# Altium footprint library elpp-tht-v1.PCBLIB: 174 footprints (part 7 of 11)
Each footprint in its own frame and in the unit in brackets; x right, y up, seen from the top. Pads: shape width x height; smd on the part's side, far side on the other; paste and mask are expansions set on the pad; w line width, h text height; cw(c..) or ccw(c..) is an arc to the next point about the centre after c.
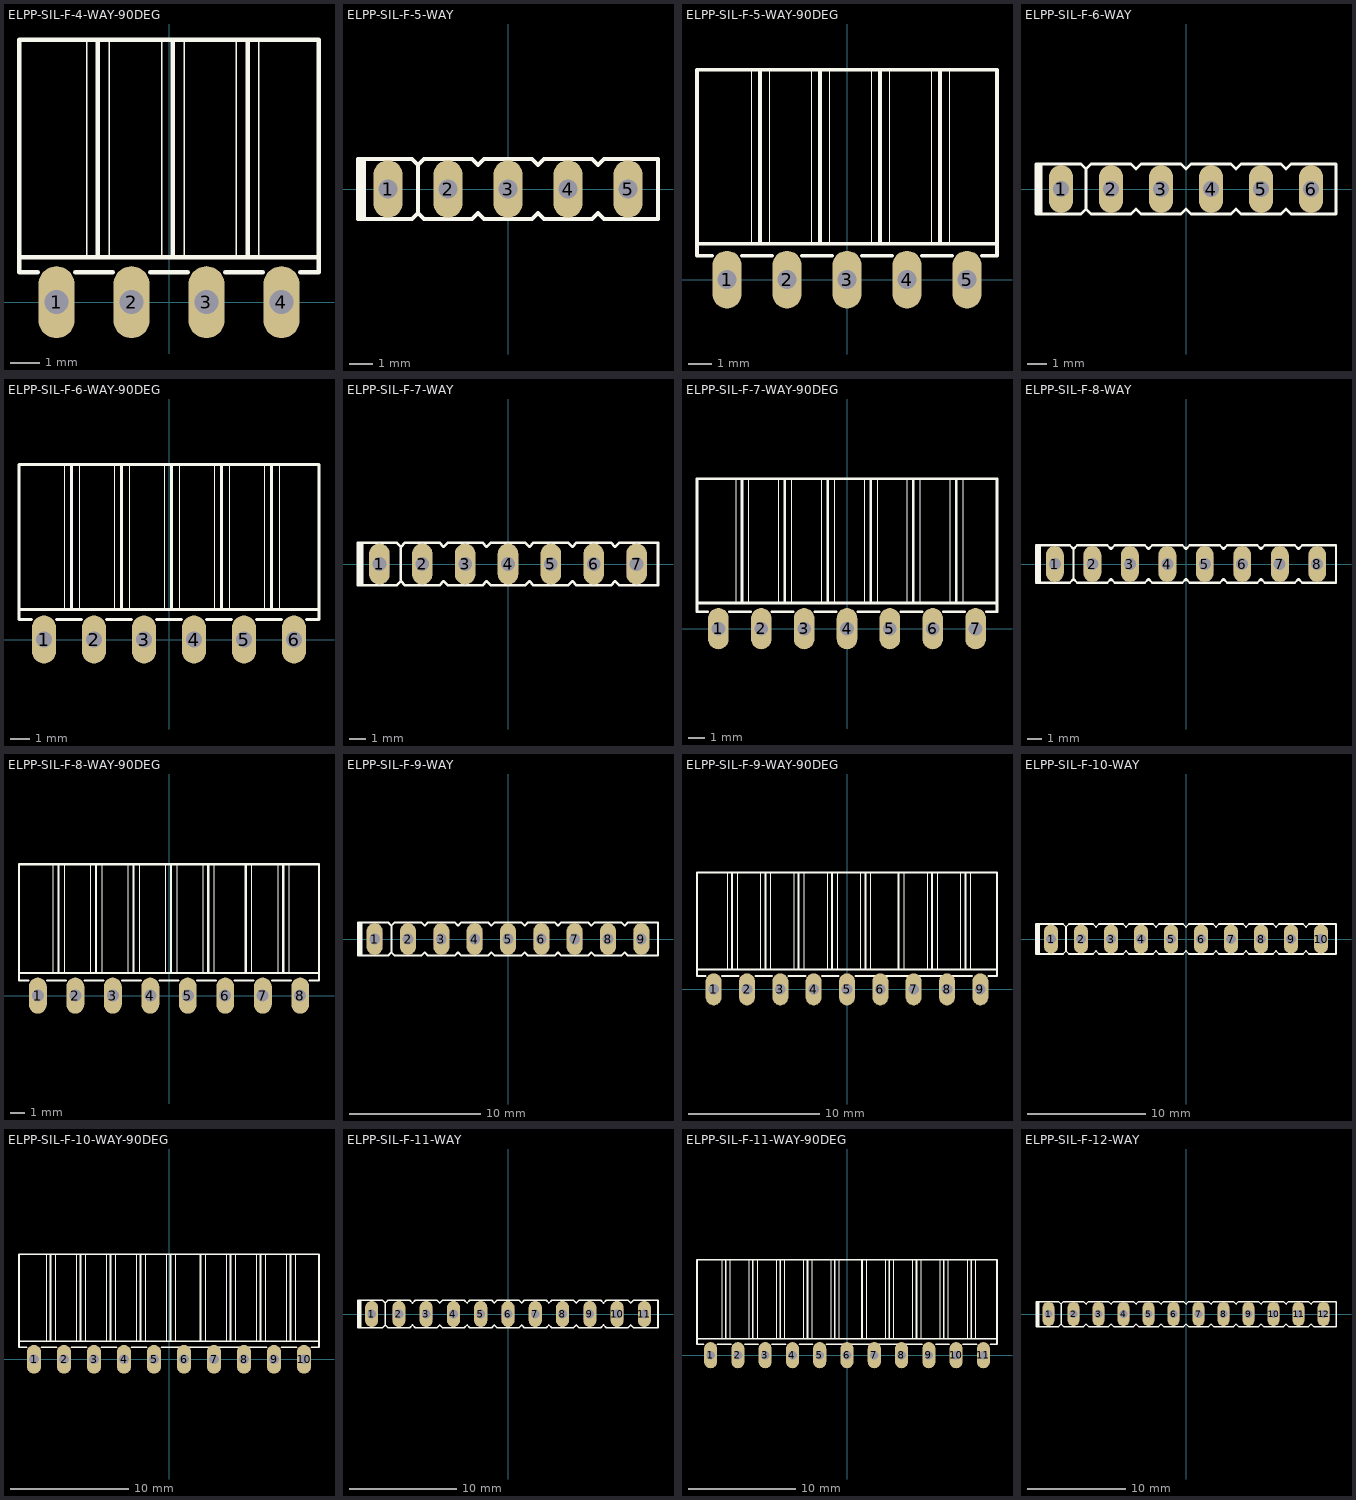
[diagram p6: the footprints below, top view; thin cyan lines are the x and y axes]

## ELPP-SIL-F-4-WAY-90DEG [mil]
pads (4):
  oval 48x96 hole 32: 1(-150,0) 2(-50,0) 3(50,0) 4(150,0)
Top Overlay:
  lines w2: -110,60 -110,350 ; -80,60 -80,350 ; -10,60 -10,350 ; 20,60 20,350 ; 90,60 90,350 ; 120,60 120,350
  lines w6: -175,40 -200,40 -200,60 ; -125,40 -75,40 ; -25,40 25,40 ; 75,40 125,40 ; 175,40 200,40 200,60 ; -200,60 -200,350 -110,350 -95,350 ; -200,60 -110,60 -95,60 ; -95,60 -80,60 -10,60 5,60 ; -95,60 -95,350 ; -95,350 -80,350 -10,350 5,350 ; 5,60 20,60 90,60 105,60 ; 5,60 5,350 ; 5,350 20,350 90,350 105,350 ; 105,60 120,60 200,60 ; 105,60 105,350 ; 105,350 120,350 200,350 200,60
Mechanical 2:
  text ">NAME" at -220,40 h42.5
Mechanical 4:
  text ">VALUE" at -150,-110 h42.5
Mechanical 16:
  rectangle: -160,0 -140,40
  rectangle: -60,0 -40,40
  rectangle: 40,0 60,40
  rectangle: 140,0 160,40
  text "2" at -20,100 h77.5
  text "3" at 80,100 h77.5
  text "4" at 180,100 h77.5
  text "1" at -120,100 h77.5

## ELPP-SIL-F-5-WAY [mil]
pads (5):
  oval 48x96 hole 32: 1(-200,0) 2(-100,0) 3(0,0) 4(100,0) 5(200,0)
Top Overlay:
  lines w6: -245,-50 -250,-50 -250,50 -245,50 ; -245,-50 -240,-50 ; -245,-50 -245,50 ; -245,50 -240,50 ; -240,-50 -160,-50 -150,-40 ; -240,-50 -240,50 ; -240,50 -160,50 -150,40 ; -150,-40 -140,-50 -60,-50 -50,-40 -40,-50 40,-50 50,-40 60,-50 140,-50 150,-40 160,-50 250,-50 250,50 160,50 150,40 140,50 60,50 50,40 40,50 -40,50 -50,40 -60,50 -140,50 -150,40 ; -150,-40 -150,40
Mechanical 2:
  text ">NAME" at -250,65 h42.5
Mechanical 4:
  text ">VALUE" at 0,65 h42.5
Mechanical 16:
  rectangle: -205,10 -195,30
  rectangle: -205,-30 -195,-10
  rectangle: -105,10 -95,30
  rectangle: -105,-30 -95,-10
  rectangle: -5,10 5,30
  rectangle: -5,-30 5,-10
  rectangle: 95,10 105,30
  rectangle: 95,-30 105,-10
  rectangle: 195,10 205,30
  rectangle: 195,-30 205,-10
  lines w6: -220,-20 -220,20 -210,20 -210,30 -190,30 -190,20 -180,20 -180,-20 -190,-20 -190,-30 -210,-30 -210,-20 -220,-20 ; -120,-20 -120,20 -110,20 -110,30 -90,30 -90,20 -80,20 -80,-20 -90,-20 -90,-30 -110,-30 -110,-20 -120,-20 ; -20,-20 -20,20 -10,20 -10,30 10,30 10,20 20,20 20,-20 10,-20 10,-30 -10,-30 -10,-20 -20,-20 ; 80,-20 80,20 90,20 90,30 110,30 110,20 120,20 120,-20 110,-20 110,-30 90,-30 90,-20 80,-20 ; 180,-20 180,20 190,20 190,30 210,30 210,20 220,20 220,-20 210,-20 210,-30 190,-30 190,-20 180,-20

## ELPP-SIL-F-5-WAY-90DEG [mil]
pads (5):
  oval 48x96 hole 32: 1(-200,0) 2(-100,0) 3(0,0) 4(100,0) 5(200,0)
Top Overlay:
  lines w2: -160,60 -160,350 ; -130,60 -130,350 ; -60,60 -60,350 ; -30,60 -30,350 ; 40,60 40,350 ; 70,60 70,350 ; 140,60 140,350 ; 170,60 170,350
  lines w6: -225,40 -250,40 -250,60 ; -175,40 -125,40 ; -75,40 -25,40 ; 25,40 75,40 ; 125,40 175,40 ; 225,40 250,40 250,60 ; -250,60 -250,350 -160,350 -145,350 ; -250,60 -160,60 -145,60 ; -145,60 -130,60 -60,60 -45,60 ; -145,60 -145,350 ; -145,350 -130,350 -60,350 -45,350 ; -45,60 -30,60 40,60 55,60 ; -45,60 -45,350 ; -45,350 -30,350 40,350 55,350 ; 55,60 70,60 140,60 155,60 ; 55,60 55,350 ; 55,350 70,350 140,350 155,350 ; 155,60 170,60 250,60 ; 155,60 155,350 ; 155,350 170,350 250,350 250,60
Mechanical 2:
  text ">NAME" at -270,40 h42.5
Mechanical 4:
  text ">VALUE" at 310,50 h42.5
Mechanical 16:
  rectangle: -210,0 -190,40
  rectangle: -110,0 -90,40
  rectangle: -10,0 10,40
  rectangle: 90,0 110,40
  rectangle: 190,0 210,40
  text "2" at -70,100 h77.5
  text "5" at 235,100 h77.5
  text "3" at 30,100 h77.5
  text "4" at 130,100 h77.5
  text "1" at -170,100 h77.5

## ELPP-SIL-F-6-WAY [mil]
pads (6):
  oval 48x96 hole 32: 1(-250,0) 2(-150,0) 3(-50,0) 4(50,0) 5(150,0) 6(250,0)
Top Overlay:
  lines w6: -295,-50 -300,-50 -300,50 -295,50 ; -295,-50 -290,-50 ; -295,-50 -295,50 ; -295,50 -290,50 ; -290,-50 -210,-50 -200,-40 ; -290,-50 -290,50 ; -290,50 -210,50 -200,40 ; -200,-40 -190,-50 -110,-50 -100,-40 -90,-50 -10,-50 0,-40 10,-50 90,-50 100,-40 110,-50 190,-50 200,-40 210,-50 300,-50 300,50 210,50 200,40 190,50 110,50 100,40 90,50 10,50 0,40 -10,50 -90,50 -100,40 -110,50 -190,50 -200,40 ; -200,-40 -200,40
Mechanical 2:
  text ">NAME" at -300,65 h42.5
Mechanical 4:
  text ">VALUE" at 0,65 h42.5
Mechanical 16:
  rectangle: -255,10 -245,30
  rectangle: -255,-30 -245,-10
  rectangle: -155,10 -145,30
  rectangle: -155,-30 -145,-10
  rectangle: -55,10 -45,30
  rectangle: -55,-30 -45,-10
  rectangle: 45,10 55,30
  rectangle: 45,-30 55,-10
  rectangle: 145,10 155,30
  rectangle: 145,-30 155,-10
  rectangle: 245,10 255,30
  rectangle: 245,-30 255,-10
  lines w6: -270,-20 -270,20 -260,20 -260,30 -240,30 -240,20 -230,20 -230,-20 -240,-20 -240,-30 -260,-30 -260,-20 -270,-20 ; -170,-20 -170,20 -160,20 -160,30 -140,30 -140,20 -130,20 -130,-20 -140,-20 -140,-30 -160,-30 -160,-20 -170,-20 ; -70,-20 -70,20 -60,20 -60,30 -40,30 -40,20 -30,20 -30,-20 -40,-20 -40,-30 -60,-30 -60,-20 -70,-20 ; 30,-20 30,20 40,20 40,30 60,30 60,20 70,20 70,-20 60,-20 60,-30 40,-30 40,-20 30,-20 ; 130,-20 130,20 140,20 140,30 160,30 160,20 170,20 170,-20 160,-20 160,-30 140,-30 140,-20 130,-20 ; 230,-20 230,20 240,20 240,30 260,30 260,20 270,20 270,-20 260,-20 260,-30 240,-30 240,-20 230,-20

## ELPP-SIL-F-6-WAY-90DEG [mil]
pads (6):
  oval 48x96 hole 32: 1(-250,0) 2(-150,0) 3(-50,0) 4(50,0) 5(150,0) 6(250,0)
Top Overlay:
  lines w2: -210,60 -210,350 ; -180,60 -180,350 ; -110,60 -110,350 ; -80,60 -80,350 ; -10,60 -10,350 ; 20,60 20,350 ; 90,60 90,350 ; 120,60 120,350 ; 190,60 190,350 ; 220,60 220,350
  lines w6: -275,40 -300,40 -300,60 ; -225,40 -175,40 ; -125,40 -75,40 ; -25,40 25,40 ; 75,40 125,40 ; 175,40 225,40 ; 220,60 205,60 ; 220,350 205,350 ; 275,40 300,40 300,60 ; -300,60 -300,350 -210,350 -195,350 ; -300,60 -210,60 -195,60 ; -195,60 -180,60 -110,60 -95,60 ; -195,60 -195,350 ; -195,350 -180,350 -110,350 -95,350 ; -95,60 -80,60 -10,60 5,60 ; -95,60 -95,350 ; -95,350 -80,350 -10,350 5,350 ; 5,60 20,60 90,60 105,60 ; 5,60 5,350 ; 5,350 20,350 90,350 105,350 ; 105,60 120,60 ; 105,60 105,350 ; 105,350 120,350 ; 120,60 300,60 ; 120,60 190,60 205,60 ; 120,350 300,350 300,60 ; 120,350 190,350 205,350 ; 205,60 205,350
Mechanical 2:
  text ">NAME" at -320,40 h42.5
Mechanical 4:
  text ">VALUE" at 360,50 h42.5
Mechanical 16:
  rectangle: -260,0 -240,40
  rectangle: -160,0 -140,40
  rectangle: -60,0 -40,40
  rectangle: 40,0 60,40
  rectangle: 140,0 160,40
  rectangle: 240,0 260,40
  text "2" at -120,100 h77.5
  text "5" at 185,100 h77.5
  text "3" at -20,100 h77.5
  text "4" at 80,100 h77.5
  text "1" at -220,100 h77.5
  text "6" at 285,100 h77.5

## ELPP-SIL-F-7-WAY [mil]
pads (7):
  oval 48x96 hole 32: 1(-300,0) 2(-200,0) 3(-100,0) 4(0,0) 5(100,0) 6(200,0) 7(300,0)
Top Overlay:
  lines w6: -345,-50 -350,-50 -350,50 -345,50 ; -345,-50 -340,-50 ; -345,-50 -345,50 ; -345,50 -340,50 ; -340,-50 -260,-50 -250,-40 ; -340,-50 -340,50 ; -340,50 -260,50 -250,40 ; -250,-40 -240,-50 -160,-50 -150,-40 -140,-50 -60,-50 -50,-40 -40,-50 40,-50 50,-40 60,-50 140,-50 150,-40 160,-50 240,-50 250,-40 260,-50 350,-50 350,50 260,50 250,40 240,50 160,50 150,40 140,50 60,50 50,40 40,50 -40,50 -50,40 -60,50 -140,50 -150,40 -160,50 -240,50 -250,40 ; -250,-40 -250,40
Mechanical 2:
  text ">NAME" at -350,65 h42.5
Mechanical 4:
  text ">VALUE" at 50,65 h42.5
Mechanical 16:
  rectangle: -305,10 -295,30
  rectangle: -305,-30 -295,-10
  rectangle: -205,10 -195,30
  rectangle: -205,-30 -195,-10
  rectangle: -105,10 -95,30
  rectangle: -105,-30 -95,-10
  rectangle: -5,10 5,30
  rectangle: -5,-30 5,-10
  rectangle: 95,10 105,30
  rectangle: 95,-30 105,-10
  rectangle: 195,10 205,30
  rectangle: 195,-30 205,-10
  rectangle: 295,10 305,30
  rectangle: 295,-30 305,-10
  lines w6: -320,-20 -320,20 -310,20 -310,30 -290,30 -290,20 -280,20 -280,-20 -290,-20 -290,-30 -310,-30 -310,-20 -320,-20 ; -220,-20 -220,20 -210,20 -210,30 -190,30 -190,20 -180,20 -180,-20 -190,-20 -190,-30 -210,-30 -210,-20 -220,-20 ; -120,-20 -120,20 -110,20 -110,30 -90,30 -90,20 -80,20 -80,-20 -90,-20 -90,-30 -110,-30 -110,-20 -120,-20 ; -20,-20 -20,20 -10,20 -10,30 10,30 10,20 20,20 20,-20 10,-20 10,-30 -10,-30 -10,-20 -20,-20 ; 80,-20 80,20 90,20 90,30 110,30 110,20 120,20 120,-20 110,-20 110,-30 90,-30 90,-20 80,-20 ; 180,-20 180,20 190,20 190,30 210,30 210,20 220,20 220,-20 210,-20 210,-30 190,-30 190,-20 180,-20 ; 280,-20 280,20 290,20 290,30 310,30 310,20 320,20 320,-20 310,-20 310,-30 290,-30 290,-20 280,-20

## ELPP-SIL-F-7-WAY-90DEG [mil]
pads (7):
  oval 48x96 hole 32: 1(-300,0) 2(-200,0) 3(-100,0) 4(0,0) 5(100,0) 6(200,0) 7(300,0)
Top Overlay:
  lines w2: -260,60 -260,350 ; -230,60 -230,350 ; -160,60 -160,350 ; -130,60 -130,350 ; -60,60 -60,350 ; -30,60 -30,350 ; 40,60 40,350 ; 70,60 70,350 ; 140,60 140,350 ; 170,60 170,350 ; 240,60 240,350 ; 270,60 270,350
  lines w6: -325,40 -350,40 -350,60 ; -275,40 -225,40 ; -175,40 -125,40 ; -75,40 -25,40 ; 25,40 75,40 ; 125,40 175,40 ; 170,60 155,60 ; 170,350 155,350 ; 225,40 275,40 ; 255,350 255,60 ; 270,60 255,60 ; 325,40 350,40 350,60 ; -350,60 -350,350 -260,350 -245,350 ; -350,60 -260,60 -245,60 ; -245,60 -230,60 -160,60 -145,60 ; -245,60 -245,350 ; -245,350 -230,350 -160,350 -145,350 ; -145,60 -130,60 -60,60 -45,60 ; -145,60 -145,350 ; -145,350 -130,350 -60,350 -45,350 ; -45,60 -30,60 40,60 55,60 ; -45,60 -45,350 ; -45,350 -30,350 40,350 55,350 ; 55,60 70,60 ; 55,60 55,350 ; 55,350 70,350 ; 70,60 240,60 ; 70,60 140,60 155,60 ; 70,350 240,350 350,350 350,60 ; 70,350 140,350 155,350 ; 155,60 155,350 ; 240,60 350,60 ; 240,60 255,60
Mechanical 2:
  text ">NAME" at -370,40 h42.5
Mechanical 4:
  text ">VALUE" at 410,50 h42.5
Mechanical 16:
  rectangle: -310,0 -290,40
  rectangle: -210,0 -190,40
  rectangle: -110,0 -90,40
  rectangle: -10,0 10,40
  rectangle: 90,0 110,40
  rectangle: 190,0 210,40
  rectangle: 290,0 310,40
  text "2" at -170,100 h77.5
  text "5" at 135,100 h77.5
  text "3" at -70,100 h77.5
  text "4" at 30,100 h77.5
  text "1" at -270,100 h77.5
  text "6" at 235,100 h77.5
  text "7" at 335,100 h77.5

## ELPP-SIL-F-8-WAY [mil]
pads (8):
  oval 48x96 hole 32: 1(-350,0) 2(-250,0) 3(-150,0) 4(-50,0) 5(50,0) 6(150,0) 7(250,0) 8(350,0)
Top Overlay:
  lines w6: -395,-50 -400,-50 -400,50 -395,50 ; -395,-50 -390,-50 ; -395,-50 -395,50 ; -395,50 -390,50 ; -390,-50 -310,-50 -300,-40 ; -390,-50 -390,50 ; -390,50 -310,50 -300,40 ; -300,-40 -290,-50 -210,-50 -200,-40 -190,-50 -110,-50 -100,-40 -90,-50 -10,-50 0,-40 10,-50 90,-50 100,-40 110,-50 190,-50 200,-40 210,-50 290,-50 300,-40 310,-50 400,-50 400,50 310,50 300,40 290,50 210,50 200,40 190,50 110,50 100,40 90,50 10,50 0,40 -10,50 -90,50 -100,40 -110,50 -190,50 -200,40 -210,50 -290,50 -300,40 ; -300,-40 -300,40
Mechanical 2:
  text ">NAME" at -400,65 h42.5
Mechanical 4:
  text ">VALUE" at 100,65 h42.5
Mechanical 16:
  rectangle: -355,10 -345,30
  rectangle: -355,-30 -345,-10
  rectangle: -255,10 -245,30
  rectangle: -255,-30 -245,-10
  rectangle: -155,10 -145,30
  rectangle: -155,-30 -145,-10
  rectangle: -55,10 -45,30
  rectangle: -55,-30 -45,-10
  rectangle: 45,10 55,30
  rectangle: 45,-30 55,-10
  rectangle: 145,10 155,30
  rectangle: 145,-30 155,-10
  rectangle: 245,10 255,30
  rectangle: 245,-30 255,-10
  rectangle: 345,10 355,30
  rectangle: 345,-30 355,-10
  lines w6: -370,-20 -370,20 -360,20 -360,30 -340,30 -340,20 -330,20 -330,-20 -340,-20 -340,-30 -360,-30 -360,-20 -370,-20 ; -270,-20 -270,20 -260,20 -260,30 -240,30 -240,20 -230,20 -230,-20 -240,-20 -240,-30 -260,-30 -260,-20 -270,-20 ; -170,-20 -170,20 -160,20 -160,30 -140,30 -140,20 -130,20 -130,-20 -140,-20 -140,-30 -160,-30 -160,-20 -170,-20 ; -70,-20 -70,20 -60,20 -60,30 -40,30 -40,20 -30,20 -30,-20 -40,-20 -40,-30 -60,-30 -60,-20 -70,-20 ; 30,-20 30,20 40,20 40,30 60,30 60,20 70,20 70,-20 60,-20 60,-30 40,-30 40,-20 30,-20 ; 130,-20 130,20 140,20 140,30 160,30 160,20 170,20 170,-20 160,-20 160,-30 140,-30 140,-20 130,-20 ; 230,-20 230,20 240,20 240,30 260,30 260,20 270,20 270,-20 260,-20 260,-30 240,-30 240,-20 230,-20 ; 330,-20 330,20 340,20 340,30 360,30 360,20 370,20 370,-20 360,-20 360,-30 340,-30 340,-20 330,-20

## ELPP-SIL-F-8-WAY-90DEG [mil]
pads (8):
  oval 48x96 hole 32: 1(-350,0) 2(-250,0) 3(-150,0) 4(-50,0) 5(50,0) 6(150,0) 7(250,0) 8(350,0)
Top Overlay:
  lines w2: -310,60 -310,350 ; -280,60 -280,350 ; -210,60 -210,350 ; -180,60 -180,350 ; -110,60 -110,350 ; -80,60 -80,350 ; -10,60 -10,350 ; 20,60 20,350 ; 90,60 90,350 ; 120,60 120,350 ; 220,60 220,350 ; 290,60 290,350 ; 320,60 320,350
  lines w6: -375,40 -400,40 -400,60 ; -325,40 -275,40 ; -225,40 -175,40 ; -125,40 -75,40 ; -25,40 25,40 ; 75,40 125,40 ; 120,60 105,60 ; 120,350 105,350 ; 175,40 225,40 ; 190,60 205,60 ; 205,350 205,60 ; 275,40 325,40 ; 305,350 305,60 ; 320,60 305,60 ; 375,40 400,40 400,60 ; -400,60 -400,350 -310,350 -295,350 ; -400,60 -310,60 -295,60 ; -295,60 -280,60 -210,60 -195,60 ; -295,60 -295,350 ; -295,350 -280,350 -210,350 -195,350 ; -195,60 -180,60 -110,60 -95,60 ; -195,60 -195,350 ; -195,350 -180,350 -110,350 -95,350 ; -95,60 -80,60 -10,60 5,60 ; -95,60 -95,350 ; -95,350 -80,350 -10,350 5,350 ; 5,60 20,60 ; 5,60 5,350 ; 5,350 20,350 ; 20,60 400,60 ; 20,60 90,60 105,60 ; 20,350 400,350 400,60 ; 20,350 90,350 105,350 ; 105,60 105,350 ; 205,60 220,60 290,60 305,60
Mechanical 2:
  text ">NAME" at -420,40 h42.5
Mechanical 4:
  text ">VALUE" at 460,50 h42.5
Mechanical 16:
  rectangle: -360,0 -340,40
  rectangle: -260,0 -240,40
  rectangle: -160,0 -140,40
  rectangle: -60,0 -40,40
  rectangle: 40,0 60,40
  rectangle: 140,0 160,40
  rectangle: 240,0 260,40
  rectangle: 340,0 360,40
  text "2" at -220,100 h77.5
  text "5" at 85,100 h77.5
  text "3" at -120,100 h77.5
  text "4" at -20,100 h77.5
  text "1" at -320,100 h77.5
  text "6" at 185,100 h77.5
  text "7" at 285,100 h77.5
  text "8" at 385,100 h77.5

## ELPP-SIL-F-9-WAY [mil]
pads (9):
  oval 48x96 hole 32: 1(-400,0) 2(-300,0) 3(-200,0) 4(-100,0) 5(0,0) 6(100,0) 7(200,0) 8(300,0) 9(400,0)
Top Overlay:
  lines w6: -445,-50 -450,-50 -450,50 -445,50 ; -445,-50 -440,-50 ; -445,-50 -445,50 ; -445,50 -440,50 ; -440,-50 -360,-50 -350,-40 ; -440,-50 -440,50 ; -440,50 -360,50 -350,40 ; -350,-40 -340,-50 -260,-50 -250,-40 -240,-50 -160,-50 -150,-40 -140,-50 -60,-50 -50,-40 -40,-50 40,-50 50,-40 60,-50 140,-50 150,-40 160,-50 240,-50 250,-40 260,-50 340,-50 350,-40 360,-50 450,-50 450,50 360,50 350,40 340,50 260,50 250,40 240,50 160,50 150,40 140,50 60,50 50,40 40,50 -40,50 -50,40 -60,50 -140,50 -150,40 -160,50 -240,50 -250,40 -260,50 -340,50 -350,40 ; -350,-40 -350,40
Mechanical 2:
  text ">NAME" at -450,65 h42.5
Mechanical 4:
  text ">VALUE" at 150,65 h42.5
Mechanical 16:
  rectangle: -405,10 -395,30
  rectangle: -405,-30 -395,-10
  rectangle: -305,10 -295,30
  rectangle: -305,-30 -295,-10
  rectangle: -205,10 -195,30
  rectangle: -205,-30 -195,-10
  rectangle: -105,10 -95,30
  rectangle: -105,-30 -95,-10
  rectangle: -5,10 5,30
  rectangle: -5,-30 5,-10
  rectangle: 95,10 105,30
  rectangle: 95,-30 105,-10
  rectangle: 195,10 205,30
  rectangle: 195,-30 205,-10
  rectangle: 295,10 305,30
  rectangle: 295,-30 305,-10
  rectangle: 395,10 405,30
  rectangle: 395,-30 405,-10
  lines w6: -420,-20 -420,20 -410,20 -410,30 -390,30 -390,20 -380,20 -380,-20 -390,-20 -390,-30 -410,-30 -410,-20 -420,-20 ; -320,-20 -320,20 -310,20 -310,30 -290,30 -290,20 -280,20 -280,-20 -290,-20 -290,-30 -310,-30 -310,-20 -320,-20 ; -220,-20 -220,20 -210,20 -210,30 -190,30 -190,20 -180,20 -180,-20 -190,-20 -190,-30 -210,-30 -210,-20 -220,-20 ; -120,-20 -120,20 -110,20 -110,30 -90,30 -90,20 -80,20 -80,-20 -90,-20 -90,-30 -110,-30 -110,-20 -120,-20 ; -20,-20 -20,20 -10,20 -10,30 10,30 10,20 20,20 20,-20 10,-20 10,-30 -10,-30 -10,-20 -20,-20 ; 80,-20 80,20 90,20 90,30 110,30 110,20 120,20 120,-20 110,-20 110,-30 90,-30 90,-20 80,-20 ; 180,-20 180,20 190,20 190,30 210,30 210,20 220,20 220,-20 210,-20 210,-30 190,-30 190,-20 180,-20 ; 280,-20 280,20 290,20 290,30 310,30 310,20 320,20 320,-20 310,-20 310,-30 290,-30 290,-20 280,-20 ; 380,-20 380,20 390,20 390,30 410,30 410,20 420,20 420,-20 410,-20 410,-30 390,-30 390,-20 380,-20

## ELPP-SIL-F-9-WAY-90DEG [mil]
pads (9):
  oval 48x96 hole 32: 1(-400,0) 2(-300,0) 3(-200,0) 4(-100,0) 5(0,0) 6(100,0) 7(200,0) 8(300,0) 9(400,0)
Top Overlay:
  lines w2: -360,60 -360,350 ; -330,60 -330,350 ; -260,60 -260,350 ; -230,60 -230,350 ; -160,60 -160,350 ; -130,60 -130,350 ; -60,60 -60,350 ; -30,60 -30,350 ; 40,60 40,350 ; 70,60 70,350 ; 170,60 170,350 ; 240,60 240,350 ; 270,60 270,350 ; 340,60 340,350 ; 370,60 370,350
  lines w6: -425,40 -450,40 -450,60 ; -375,40 -325,40 ; -275,40 -225,40 ; -175,40 -125,40 ; -75,40 -25,40 ; 70,60 55,60 ; 70,350 55,350 ; 75,40 25,40 350,40 375,40 ; 125,40 175,40 ; 140,60 155,60 ; 155,350 155,60 ; 225,40 275,40 ; 255,350 255,60 ; 270,60 255,60 ; 425,40 450,40 450,60 ; 440,350 370,350 ; -450,60 -450,350 -360,350 -345,350 ; -450,60 -360,60 -345,60 ; -345,60 -330,60 -260,60 -245,60 ; -345,60 -345,350 ; -345,350 -330,350 -260,350 -245,350 ; -245,60 -230,60 -160,60 -145,60 ; -245,60 -245,350 ; -245,350 -230,350 -160,350 -145,350 ; -145,60 -130,60 -60,60 -45,60 ; -145,60 -145,350 ; -145,350 -130,350 -60,350 -45,350 ; -45,60 -30,60 ; -45,60 -45,350 ; -45,350 -30,350 ; -30,60 340,60 350,60 355,60 ; -30,60 40,60 55,60 ; -30,350 340,350 350,350 355,350 ; -30,350 40,350 55,350 ; 55,60 55,350 ; 155,60 170,60 240,60 255,60 ; 355,60 370,60 450,60 ; 355,60 355,350 ; 355,350 370,350 ; 370,350 450,350 450,60
Mechanical 2:
  text ">NAME" at -470,40 h42.5
Mechanical 4:
  text ">VALUE" at 510,50 h42.5
Mechanical 16:
  rectangle: -410,0 -390,40
  rectangle: -310,0 -290,40
  rectangle: -210,0 -190,40
  rectangle: -110,0 -90,40
  rectangle: -10,0 10,40
  rectangle: 90,0 110,40
  rectangle: 190,0 210,40
  rectangle: 290,0 310,40
  rectangle: 390,0 410,40
  text "2" at -270,100 h77.5
  text "5" at 35,100 h77.5
  text "3" at -170,100 h77.5
  text "4" at -70,100 h77.5
  text "1" at -370,100 h77.5
  text "6" at 135,100 h77.5
  text "7" at 235,100 h77.5
  text "8" at 335,100 h77.5
  text "9" at 430,100 h77.5

## ELPP-SIL-F-10-WAY [mil]
pads (10):
  oval 48x96 hole 32: 1(-450,0) 2(-350,0) 3(-250,0) 4(-150,0) 5(-50,0) 6(50,0) 7(150,0) 8(250,0) 9(350,0) 10(450,0)
Top Overlay:
  lines w6: -495,-50 -500,-50 -500,50 -495,50 ; -495,-50 -490,-50 ; -495,-50 -495,50 ; -495,50 -490,50 ; -490,-50 -410,-50 -400,-40 ; -490,-50 -490,50 ; -490,50 -410,50 -400,40 ; -400,-40 -390,-50 -310,-50 -300,-40 -290,-50 -210,-50 -200,-40 -190,-50 -110,-50 -100,-40 -90,-50 -10,-50 0,-40 10,-50 90,-50 100,-40 110,-50 190,-50 200,-40 210,-50 290,-50 300,-40 310,-50 390,-50 400,-40 410,-50 500,-50 500,50 410,50 400,40 390,50 310,50 300,40 290,50 210,50 200,40 190,50 110,50 100,40 90,50 10,50 0,40 -10,50 -90,50 -100,40 -110,50 -190,50 -200,40 -210,50 -290,50 -300,40 -310,50 -390,50 -400,40 ; -400,-40 -400,40
Mechanical 2:
  text ">NAME" at -500,65 h42.5
Mechanical 4:
  text ">VALUE" at 200,65 h42.5
Mechanical 16:
  rectangle: -455,10 -445,30
  rectangle: -455,-30 -445,-10
  rectangle: -355,10 -345,30
  rectangle: -355,-30 -345,-10
  rectangle: -255,10 -245,30
  rectangle: -255,-30 -245,-10
  rectangle: -155,10 -145,30
  rectangle: -155,-30 -145,-10
  rectangle: -55,10 -45,30
  rectangle: -55,-30 -45,-10
  rectangle: 45,10 55,30
  rectangle: 45,-30 55,-10
  rectangle: 145,10 155,30
  rectangle: 145,-30 155,-10
  rectangle: 245,10 255,30
  rectangle: 245,-30 255,-10
  rectangle: 345,10 355,30
  rectangle: 345,-30 355,-10
  rectangle: 445,10 455,30
  rectangle: 445,-30 455,-10
  lines w6: -470,-20 -470,20 -460,20 -460,30 -440,30 -440,20 -430,20 -430,-20 -440,-20 -440,-30 -460,-30 -460,-20 -470,-20 ; -370,-20 -370,20 -360,20 -360,30 -340,30 -340,20 -330,20 -330,-20 -340,-20 -340,-30 -360,-30 -360,-20 -370,-20 ; -270,-20 -270,20 -260,20 -260,30 -240,30 -240,20 -230,20 -230,-20 -240,-20 -240,-30 -260,-30 -260,-20 -270,-20 ; -170,-20 -170,20 -160,20 -160,30 -140,30 -140,20 -130,20 -130,-20 -140,-20 -140,-30 -160,-30 -160,-20 -170,-20 ; -70,-20 -70,20 -60,20 -60,30 -40,30 -40,20 -30,20 -30,-20 -40,-20 -40,-30 -60,-30 -60,-20 -70,-20 ; 30,-20 30,20 40,20 40,30 60,30 60,20 70,20 70,-20 60,-20 60,-30 40,-30 40,-20 30,-20 ; 130,-20 130,20 140,20 140,30 160,30 160,20 170,20 170,-20 160,-20 160,-30 140,-30 140,-20 130,-20 ; 230,-20 230,20 240,20 240,30 260,30 260,20 270,20 270,-20 260,-20 260,-30 240,-30 240,-20 230,-20 ; 330,-20 330,20 340,20 340,30 360,30 360,20 370,20 370,-20 360,-20 360,-30 340,-30 340,-20 330,-20 ; 430,-20 430,20 440,20 440,30 460,30 460,20 470,20 470,-20 460,-20 460,-30 440,-30 440,-20 430,-20

## ELPP-SIL-F-10-WAY-90DEG [mil]
pads (10):
  oval 48x96 hole 32: 1(-450,0) 2(-350,0) 3(-250,0) 4(-150,0) 5(-50,0) 6(50,0) 7(150,0) 8(250,0) 9(350,0) 10(450,0)
Top Overlay:
  lines w2: -410,60 -410,350 ; -380,60 -380,350 ; -310,60 -310,350 ; -280,60 -280,350 ; -210,60 -210,350 ; -180,60 -180,350 ; -110,60 -110,350 ; -80,60 -80,350 ; -10,60 -10,350 ; 20,60 20,350 ; 120,60 120,350 ; 190,60 190,350 ; 220,60 220,350 ; 290,60 290,350 ; 320,60 320,350 ; 390,60 390,350 ; 420,60 420,350
  lines w6: -475,40 -500,40 -500,60 ; -425,40 -375,40 ; -325,40 -275,40 ; -225,40 -175,40 ; -125,40 -75,40 ; 20,60 5,60 ; 20,350 5,350 ; 25,40 -25,40 300,40 325,40 ; 75,40 125,40 ; 90,60 105,60 ; 105,350 105,60 ; 175,40 225,40 ; 205,350 205,60 ; 220,60 205,60 ; 375,40 425,40 ; 475,40 500,40 500,60 ; -500,60 -500,350 -410,350 -395,350 ; -500,60 -410,60 -395,60 ; -395,60 -380,60 -310,60 -295,60 ; -395,60 -395,350 ; -395,350 -380,350 -310,350 -295,350 ; -295,60 -280,60 -210,60 -195,60 ; -295,60 -295,350 ; -295,350 -280,350 -210,350 -195,350 ; -195,60 -180,60 -110,60 -95,60 ; -195,60 -195,350 ; -195,350 -180,350 -110,350 -95,350 ; -95,60 -80,60 ; -95,60 -95,350 ; -95,350 -80,350 ; -80,60 290,60 300,60 305,60 ; -80,60 -10,60 5,60 ; -80,350 290,350 300,350 305,350 ; -80,350 -10,350 5,350 ; 5,60 5,350 ; 105,60 120,60 190,60 205,60 ; 305,60 320,60 390,60 405,60 ; 305,60 305,350 ; 305,350 320,350 390,350 405,350 ; 405,60 420,60 500,60 ; 405,60 405,350 ; 405,350 420,350 500,350 500,60
Mechanical 2:
  text ">NAME" at -520,40 h42.5
Mechanical 4:
  text ">VALUE" at 560,50 h42.5
Mechanical 16:
  rectangle: -460,0 -440,40
  rectangle: -360,0 -340,40
  rectangle: -260,0 -240,40
  rectangle: -160,0 -140,40
  rectangle: -60,0 -40,40
  rectangle: 40,0 60,40
  rectangle: 140,0 160,40
  rectangle: 240,0 260,40
  rectangle: 340,0 360,40
  rectangle: 440,0 460,40
  text "2" at -320,100 h77.5
  text "5" at -15,100 h77.5
  text "3" at -220,100 h77.5
  text "4" at -120,100 h77.5
  text "1" at -420,100 h77.5
  text "6" at 85,100 h77.5
  text "7" at 185,100 h77.5
  text "8" at 285,100 h77.5
  text "10" at 480,100 h77.5
  text "9" at 380,100 h77.5

## ELPP-SIL-F-11-WAY [mil]
pads (11):
  oval 48x96 hole 32: 1(-500,0) 2(-400,0) 3(-300,0) 4(-200,0) 5(-100,0) 6(0,0) 7(100,0) 8(200,0) 9(300,0) 10(400,0) 11(500,0)
Top Overlay:
  lines w6: -545,-50 -550,-50 -550,50 -545,50 ; -545,-50 -540,-50 ; -545,-50 -545,50 ; -545,50 -540,50 ; -540,-50 -460,-50 -450,-40 ; -540,-50 -540,50 ; -540,50 -460,50 -450,40 ; -450,-40 -440,-50 -360,-50 -350,-40 -340,-50 -260,-50 -250,-40 -240,-50 -160,-50 -150,-40 -140,-50 -60,-50 -50,-40 -40,-50 40,-50 50,-40 60,-50 140,-50 150,-40 160,-50 240,-50 250,-40 260,-50 340,-50 350,-40 360,-50 440,-50 450,-40 460,-50 550,-50 550,50 460,50 450,40 440,50 360,50 350,40 340,50 260,50 250,40 240,50 160,50 150,40 140,50 60,50 50,40 40,50 -40,50 -50,40 -60,50 -140,50 -150,40 -160,50 -240,50 -250,40 -260,50 -340,50 -350,40 -360,50 -440,50 -450,40 ; -450,-40 -450,40
Mechanical 2:
  text ">NAME" at -550,65 h42.5
Mechanical 4:
  text ">VALUE" at 250,65 h42.5
Mechanical 16:
  drawing of 154 lines, arcs and shapes, not listed

## ELPP-SIL-F-11-WAY-90DEG [mil]
pads (11):
  oval 48x96 hole 32: 1(-500,0) 2(-400,0) 3(-300,0) 4(-200,0) 5(-100,0) 6(0,0) 7(100,0) 8(200,0) 9(300,0) 10(400,0) 11(500,0)
Top Overlay:
  lines w2: -460,60 -460,350 ; -430,60 -430,350 ; -360,60 -360,350 ; -330,60 -330,350 ; -260,60 -260,350 ; -230,60 -230,350 ; -160,60 -160,350 ; -130,60 -130,350 ; -60,60 -60,350 ; -30,60 -30,350 ; 70,60 70,350 ; 140,60 140,350 ; 170,60 170,350 ; 240,60 240,350 ; 270,60 270,350 ; 340,60 340,350 ; 370,60 370,350 ; 440,60 440,350 ; 470,60 470,350
  lines w6: -525,40 -550,40 -550,60 ; -475,40 -425,40 ; -375,40 -325,40 ; -275,40 -225,40 ; -175,40 -125,40 ; -30,60 -45,60 ; -30,350 -45,350 ; -25,40 -75,40 250,40 275,40 ; 25,40 75,40 ; 40,60 55,60 ; 55,350 55,60 ; 125,40 175,40 ; 155,350 155,60 ; 170,60 155,60 ; 325,40 375,40 ; 425,40 475,40 ; 525,40 550,40 550,60 ; -550,60 -550,350 -460,350 -445,350 ; -550,60 -460,60 -445,60 ; -445,60 -430,60 -360,60 -345,60 ; -445,60 -445,350 ; -445,350 -430,350 -360,350 -345,350 ; -345,60 -330,60 -260,60 -245,60 ; -345,60 -345,350 ; -345,350 -330,350 -260,350 -245,350 ; -245,60 -230,60 -160,60 -145,60 ; -245,60 -245,350 ; -245,350 -230,350 -160,350 -145,350 ; -145,60 -130,60 ; -145,60 -145,350 ; -145,350 -130,350 ; -130,60 240,60 250,60 255,60 ; -130,60 -60,60 -45,60 ; -130,350 240,350 250,350 255,350 ; -130,350 -60,350 -45,350 ; -45,60 -45,350 ; 55,60 70,60 140,60 155,60 ; 255,60 270,60 340,60 355,60 ; 255,60 255,350 ; 255,350 270,350 340,350 355,350 ; 355,60 370,60 440,60 455,60 ; 355,60 355,350 ; 355,350 370,350 440,350 455,350 ; 455,60 470,60 550,60 ; 455,60 455,350 ; 455,350 470,350 550,350 550,60
Mechanical 2:
  text ">NAME" at -570,40 h42.5
Mechanical 4:
  text ">VALUE" at 610,50 h42.5
Mechanical 16:
  rectangle: -510,0 -490,40
  rectangle: -410,0 -390,40
  rectangle: -310,0 -290,40
  rectangle: -210,0 -190,40
  rectangle: -110,0 -90,40
  rectangle: -10,0 10,40
  rectangle: 90,0 110,40
  rectangle: 190,0 210,40
  rectangle: 290,0 310,40
  rectangle: 390,0 410,40
  rectangle: 490,0 510,40
  text "2" at -370,100 h77.5
  text "5" at -65,100 h77.5
  text "3" at -270,100 h77.5
  text "4" at -170,100 h77.5
  text "1" at -470,100 h77.5
  text "6" at 35,100 h77.5
  text "7" at 135,100 h77.5
  text "8" at 235,100 h77.5
  text "10" at 430,100 h77.5
  text "11" at 530,100 h77.5
  text "9" at 330,100 h77.5

## ELPP-SIL-F-12-WAY [mil]
pads (12):
  oval 48x96 hole 32: 1(-550,0) 2(-450,0) 3(-350,0) 4(-250,0) 5(-150,0) 6(-50,0) 7(50,0) 8(150,0) 9(250,0) 10(350,0) 11(450,0) 12(550,0)
Top Overlay:
  lines w6: -595,-50 -600,-50 -600,50 -595,50 ; -595,-50 -590,-50 ; -595,-50 -595,50 ; -595,50 -590,50 ; -590,-50 -510,-50 -500,-40 ; -590,-50 -590,50 ; -590,50 -510,50 -500,40 ; -500,-40 -490,-50 -410,-50 -400,-40 -390,-50 -310,-50 -300,-40 -290,-50 -210,-50 -200,-40 -190,-50 -110,-50 -100,-40 -90,-50 -10,-50 0,-40 10,-50 90,-50 100,-40 110,-50 190,-50 200,-40 210,-50 290,-50 300,-40 310,-50 390,-50 400,-40 410,-50 490,-50 500,-40 510,-50 600,-50 600,50 510,50 500,40 490,50 410,50 400,40 390,50 310,50 300,40 290,50 210,50 200,40 190,50 110,50 100,40 90,50 10,50 0,40 -10,50 -90,50 -100,40 -110,50 -190,50 -200,40 -210,50 -290,50 -300,40 -310,50 -390,50 -400,40 -410,50 -490,50 -500,40 ; -500,-40 -500,40
Mechanical 2:
  text ">NAME" at -600,65 h42.5
Mechanical 4:
  text ">VALUE" at 300,65 h42.5
Mechanical 16:
  drawing of 168 lines, arcs and shapes, not listed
